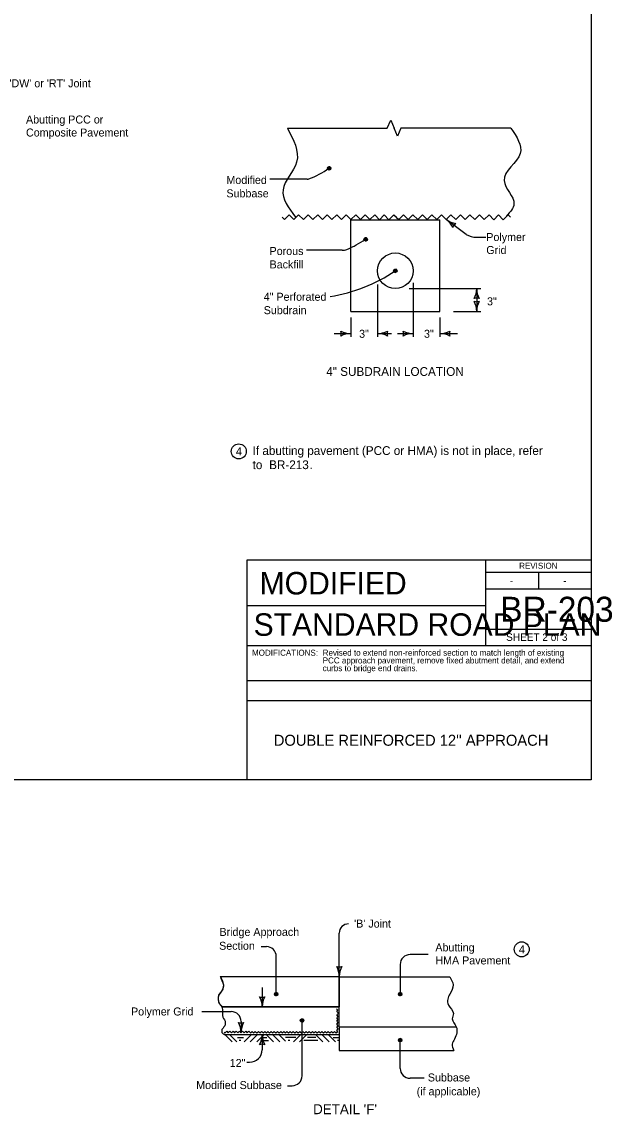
# Model space of a CAD drawing. Extents: x 5546 to 81668, y 3174 to 15999.
# Drawn here: x 15729 to 16910, y 7256 to 9440 of the extents above; entities that cross this region are included whole.
import ezdxf

# ---------------------------------------------------------------- set-up
doc = ezdxf.new("R2010")
doc.units = 0
for name, color, linetype in [('Level 61', 7, 'Continuous'), ('PS_BOLT', 7, 'Continuous'), ('PS_CONST', 7, 'Continuous'), ('PS_DIM', 7, 'Continuous'), ('PS_SHAPE', 7, 'Continuous'), ('PS_TEXT', 7, 'Continuous'), ('SheetAddenda', 7, 'Continuous'), ('tdCoLegendTitle', 7, 'Continuous'), ('tdCoShieldUsRte', 7, 'Continuous')]:
    doc.layers.add(name, color=color, linetype=linetype)

msp = doc.modelspace()

# ---------------------------------------------------------------- linework, layer by layer
at = {"layer": 'Level 61'}
msp.add_lwpolyline([(13732.5, 9944), (16867.5, 9944), (16867.5, 7924), (13732.5, 7924)], close=True, dxfattribs=at)
at = {"layer": 'PS_BOLT'}
for p, q in [((16617.8, 9014.8), (16578, 9044.5)), ((16638.4, 9009), (16656.7, 9009)), ((16440.4, 8914.6), (16440.4, 8809.9)), ((16511.7, 8918), (16511.7, 8809.9)), ((16503.4, 8906.4), (16646.9, 8906.4)), ((16638.7, 8906.4), (16638.7, 8860.8)), ((16386.9, 8848.5), (16386.9, 8809.9)), ((16565.1, 8848.5), (16565.1, 8809.9)), ((16592.5, 8860.8), (16646.9, 8860.8)), ((16353.6, 8816.4), (16386.9, 8816.4)), ((16440.4, 8816.4), (16468.3, 8816.4)), ((16480.6, 8816.4), (16511.7, 8816.4)), ((16565.1, 8816.4), (16600.3, 8816.4))]:
    msp.add_line(p, q, dxfattribs=at)
msp.add_arc((16638.4, 9048.6), 39.6, 238.7046, 270, dxfattribs=at)
at = {"layer": 'PS_CONST'}
for p, q in [((16363.9, 7530.9), (16363.9, 7617.7)), ((16207.6, 7590.7), (16218.2, 7590.7)), ((16238, 7495.7), (16238, 7570.9)), ((16542, 7574.8), (16505.5, 7574.8)), ((16485.7, 7555), (16485.7, 7495.7)), ((16209.8, 7508.8), (16209.8, 7470.4)), ((16089.2, 7460.8), (16147.8, 7460.8)), ((16167.6, 7441), (16167.6, 7418.8)), ((16289.5, 7332.3), (16289.5, 7442.8)), ((16209.8, 7414.8), (16209.8, 7384.6)), ((16485.7, 7347.3), (16485.7, 7403.7)), ((16179.2, 7359.6), (16184.8, 7359.6)), ((16533.6, 7327.5), (16505.5, 7327.5)), ((16260.7, 7312.5), (16269.7, 7312.5))]:
    msp.add_line(p, q, dxfattribs=at)
for points in [[(16240.9, 7495.4), (16240.3, 7496.6), (16239.8, 7498.4), (16237.9, 7498.8), (16236.3, 7498.5), (16234.8, 7497.4), (16235, 7495.6), (16235.2, 7493.8), (16236.7, 7492.9), (16238.2, 7492.8), (16240.2, 7493.9), (16240.4, 7495.2), (16239.9, 7497), (16238.7, 7498.5), (16237, 7498.5), (16235.6, 7497.3), (16235.5, 7495.7), (16235.8, 7493.8), (16236.8, 7493.6), (16238.1, 7493.2), (16239.6, 7494), (16239.6, 7495.4), (16239.3, 7496.9), (16238.5, 7498), (16236.9, 7497.4), (16236.1, 7496.3), (16236, 7494.8), (16236.8, 7494.4), (16237.8, 7493.9), (16239, 7494.6), (16239.2, 7495.8), (16238.7, 7496.8), (16237.6, 7496.8), (16236.8, 7496.3), (16236.5, 7495.3), (16236.9, 7494.8), (16237.5, 7494.5), (16238.4, 7495), (16238.6, 7495.7), (16238.2, 7496.4), (16237.6, 7496.3), (16237.2, 7495.8), (16237.2, 7495.1), (16237.7, 7495.1), (16238, 7495.7)], [(16488.9, 7495.5), (16488.4, 7496.6), (16487.8, 7498.4), (16485.9, 7498.8), (16484.3, 7498.5), (16482.8, 7497.4), (16483, 7495.7), (16483.2, 7493.8), (16484.7, 7493), (16486.2, 7492.8), (16488.2, 7493.9), (16488.4, 7495.2), (16487.9, 7497), (16486.8, 7498.5), (16485, 7498.5), (16483.7, 7497.3), (16483.5, 7495.7), (16483.9, 7493.8), (16484.9, 7493.6), (16486.1, 7493.2), (16487.6, 7494.1), (16487.6, 7495.4), (16487.3, 7496.9), (16486.5, 7498), (16485, 7497.4), (16484.1, 7496.3), (16484, 7494.8), (16484.9, 7494.4), (16485.8, 7493.9), (16487, 7494.7), (16487.3, 7495.8), (16486.7, 7496.8), (16485.6, 7496.9), (16484.8, 7496.3), (16484.5, 7495.3), (16484.9, 7494.8), (16485.6, 7494.5), (16486.5, 7495), (16486.6, 7495.8), (16486.2, 7496.5), (16485.6, 7496.3), (16485.2, 7495.8), (16485.2, 7495.1), (16485.8, 7495.1), (16486, 7495.7)], [(16292.7, 7442.5), (16292.2, 7443.7), (16291.6, 7445.5), (16289.8, 7445.9), (16288.2, 7445.6), (16286.7, 7444.5), (16286.8, 7442.7), (16287.1, 7440.9), (16288.5, 7440), (16290.1, 7439.9), (16292.1, 7441), (16292.2, 7442.3), (16291.8, 7444.1), (16290.6, 7445.6), (16288.9, 7445.5), (16287.5, 7444.4), (16287.3, 7442.7), (16287.7, 7440.9), (16288.7, 7440.6), (16290, 7440.3), (16291.5, 7441.1), (16291.4, 7442.5), (16291.2, 7444), (16290.3, 7445.1), (16288.8, 7444.5), (16287.9, 7443.4), (16287.9, 7441.8), (16288.7, 7441.5), (16289.6, 7441), (16290.8, 7441.7), (16291.1, 7442.9), (16290.6, 7443.9), (16289.4, 7443.9), (16288.6, 7443.4), (16288.4, 7442.4), (16288.8, 7441.9), (16289.4, 7441.6), (16290.3, 7442.1), (16290.5, 7442.8), (16290.1, 7443.5), (16289.5, 7443.4), (16289.1, 7442.9), (16289.1, 7442.2), (16289.6, 7442.2), (16289.9, 7442.8)], [(16488.9, 7403.4), (16488.4, 7404.6), (16487.8, 7406.4), (16485.9, 7406.8), (16484.3, 7406.5), (16482.8, 7405.4), (16483, 7403.6), (16483.2, 7401.8), (16484.7, 7400.9), (16486.2, 7400.8), (16488.2, 7401.9), (16488.4, 7403.2), (16487.9, 7405), (16486.8, 7406.5), (16485, 7406.5), (16483.7, 7405.3), (16483.5, 7403.7), (16483.9, 7401.8), (16484.9, 7401.6), (16486.1, 7401.2), (16487.6, 7402), (16487.6, 7403.4), (16487.3, 7404.9), (16486.5, 7406), (16485, 7405.4), (16484.1, 7404.3), (16484, 7402.8), (16484.9, 7402.4), (16485.8, 7401.9), (16487, 7402.6), (16487.3, 7403.8), (16486.7, 7404.8), (16485.6, 7404.8), (16484.8, 7404.3), (16484.5, 7403.3), (16484.9, 7402.8), (16485.6, 7402.5), (16486.5, 7403), (16486.6, 7403.7), (16486.2, 7404.4), (16485.6, 7404.3), (16485.2, 7403.8), (16485.2, 7403.1), (16485.8, 7403.1), (16486, 7403.7)]]:
    msp.add_lwpolyline(points, dxfattribs=at)
for centre in [(16237.7, 7495.7), (16485.7, 7495.7), (16289.5, 7442.8), (16485.7, 7403.7)]:
    msp.add_circle(centre, 3.47, dxfattribs=at)
for centre, radius, start, end in [((16552.5, 9010.5), 42.5, 25.1788, 53.2513), ((16603.4, 9078.6), 42.5, 233.2513, 261.3238), ((16606.5, 9023.2), 16.4, 125.5179, 160.9846), ((16382.5, 7617.7), 18.6, 90, 180), ((16218.2, 7570.9), 19.8, 0, 90), ((16505.5, 7555), 19.8, 90, 180), ((16363.9, 7566.8), 16.5, 252.2666, 287.7333), ((16321.2, 7530.9), 42.7, 360, 28.0725), ((16406.6, 7530.9), 42.7, 151.9275, 180), ((16209.8, 7506.2), 16.5, 252.2666, 287.7333), ((16167.1, 7470.4), 42.7, 360, 28.0725), ((16252.6, 7470.4), 42.7, 151.9275, 180), ((16147.8, 7441), 19.8, 0, 90), ((16167.6, 7454.6), 16.5, 252.2667, 287.7334), ((16124.8, 7418.8), 42.7, 0, 28.0725), ((16210.3, 7418.8), 42.7, 151.9275, 180), ((16167.1, 7414.8), 42.7, 331.9275, 360), ((16252.6, 7414.8), 42.7, 180, 208.0725), ((16209.8, 7378.9), 16.5, 72.2666, 107.7334), ((16505.5, 7347.3), 19.8, 180, 270), ((16269.7, 7332.3), 19.8, 270, 360)]:
    msp.add_arc(centre, radius, start, end, dxfattribs=at)
at = {"layer": 'PS_DIM'}
for p, q in [((16299.6, 9125), (16225.4, 9125)), ((16386.9, 8860.4), (16386.9, 9043.8)), ((16386.9, 9043.8), (16565.1, 9043.8)), ((16398.7, 9043.8), (16565.1, 9043.8)), ((16565.1, 8860.4), (16565.1, 9043.8)), ((16369.6, 8982.9), (16298.3, 8982.9)), ((16386.9, 8860.4), (16565.1, 8860.4)), ((16364, 7530.4), (16126.2, 7530.4)), ((16364, 7470.4), (16364, 7530.4)), ((16129, 7470.4), (16364, 7470.4)), ((16363.5, 7441.9), (16363.5, 7441.9))]:
    msp.add_line(p, q, dxfattribs=at)
for points in [[(16260.2, 9227.2), (16460, 9227.2), (16466.8, 9243.1), (16473.5, 9227.2)], [(16707.2, 9227.2), (16487.1, 9227.2), (16480.3, 9211.4), (16473.5, 9227.2)], [(16343.5, 9143.7), (16344.7, 9144.2), (16346.5, 9144.8), (16346.8, 9146.6), (16346.6, 9148.3), (16345.4, 9149.8), (16343.7, 9149.6), (16341.9, 9149.3), (16341, 9147.9), (16340.8, 9146.4), (16341.9, 9144.3), (16343.2, 9144.2), (16345.1, 9144.6), (16346.6, 9145.8), (16346.5, 9147.5), (16345.3, 9148.9), (16343.7, 9149.1), (16341.9, 9148.7), (16341.6, 9147.7), (16341.2, 9146.5), (16342.1, 9145), (16343.4, 9145), (16344.9, 9145.3), (16346, 9146.1), (16345.5, 9147.6), (16344.3, 9148.5), (16342.8, 9148.6), (16342.4, 9147.7), (16341.9, 9146.8), (16342.7, 9145.6), (16343.8, 9145.3), (16344.8, 9145.9), (16344.9, 9147), (16344.4, 9147.8), (16343.3, 9148.1), (16342.8, 9147.6), (16342.6, 9147), (16343.1, 9146.1), (16343.8, 9145.9), (16344.5, 9146.4), (16344.4, 9147), (16343.9, 9147.4), (16343.2, 9147.3), (16343.2, 9146.8), (16343.8, 9146.5)], [(16249.5, 9049.4), (16254.2, 9044.6), (16263.7, 9054.1), (16273.2, 9044.6), (16282.7, 9054.1), (16292.2, 9044.5), (16301.7, 9054), (16311.2, 9044.5), (16320.8, 9054), (16330.2, 9044.4), (16339.8, 9053.9), (16349.2, 9044.4), (16358.8, 9053.9), (16368.2, 9044.3), (16377.8, 9053.8), (16387.3, 9044.3), (16396.8, 9053.8), (16406.3, 9044.2), (16415.8, 9053.7), (16425.3, 9044.2), (16434.8, 9053.7), (16444.3, 9044.1), (16453.8, 9053.6), (16463.3, 9044.1), (16472.8, 9053.6), (16478.6, 9049)], [(16478, 9049.4), (16482.8, 9044.6), (16492.3, 9054.1), (16501.8, 9044.6), (16511.3, 9054.1), (16520.8, 9044.5), (16530.3, 9054), (16539.8, 9044.5), (16549.3, 9054), (16558.8, 9044.4), (16568.3, 9053.9), (16577.8, 9044.4), (16587.3, 9053.9), (16596.8, 9044.3), (16606.4, 9053.8), (16615.8, 9044.3), (16625.3, 9053.8), (16634.8, 9044.2), (16644.3, 9053.7), (16653.8, 9044.2), (16663.4, 9053.7), (16672.8, 9044.1), (16682.4, 9053.6), (16691.8, 9044.1), (16701.4, 9053.6), (16706.6, 9049.4)], [(16416.4, 9001.6), (16417.5, 9002.1), (16419.3, 9002.7), (16419.7, 9004.5), (16419.4, 9006.1), (16418.3, 9007.6), (16416.6, 9007.5), (16414.7, 9007.2), (16413.9, 9005.8), (16413.7, 9004.2), (16414.8, 9002.2), (16416.1, 9002.1), (16417.9, 9002.5), (16419.4, 9003.7), (16419.4, 9005.4), (16418.2, 9006.8), (16416.6, 9007), (16414.7, 9006.6), (16414.5, 9005.6), (16414.1, 9004.4), (16415, 9002.9), (16416.3, 9002.9), (16417.8, 9003.1), (16418.9, 9004), (16418.3, 9005.5), (16417.2, 9006.4), (16415.7, 9006.4), (16415.3, 9005.6), (16414.8, 9004.7), (16415.5, 9003.5), (16416.7, 9003.2), (16417.7, 9003.7), (16417.7, 9004.9), (16417.2, 9005.7), (16416.2, 9006), (16415.7, 9005.5), (16415.4, 9004.9), (16415.9, 9004), (16416.7, 9003.8), (16417.4, 9004.2), (16417.2, 9004.9), (16416.7, 9005.3), (16416, 9005.2), (16416, 9004.7), (16416.6, 9004.4)], [(16475.8, 8938.8), (16476.9, 8939.4), (16478.7, 8939.9), (16479.1, 8941.8), (16478.8, 8943.4), (16477.7, 8944.9), (16476, 8944.7), (16474.1, 8944.5), (16473.3, 8943), (16473.1, 8941.5), (16474.2, 8939.5), (16475.5, 8939.3), (16477.3, 8939.8), (16478.8, 8941), (16478.8, 8942.7), (16477.6, 8944.1), (16476, 8944.2), (16474.2, 8943.9), (16473.9, 8942.8), (16473.5, 8941.6), (16474.4, 8940.1), (16475.7, 8940.1), (16477.2, 8940.4), (16478.3, 8941.2), (16477.7, 8942.8), (16476.6, 8943.6), (16475.1, 8943.7), (16474.7, 8942.9), (16474.2, 8941.9), (16475, 8940.7), (16476.1, 8940.5), (16477.1, 8941), (16477.2, 8942.1), (16476.6, 8942.9), (16475.6, 8943.2), (16475.1, 8942.8), (16474.8, 8942.2), (16475.3, 8941.3), (16476.1, 8941.1), (16476.8, 8941.5), (16476.6, 8942.1), (16476.1, 8942.5), (16475.4, 8942.5), (16475.4, 8942), (16476, 8941.7)]]:
    msp.add_lwpolyline(points, dxfattribs=at)
for centre, radius in [((16343.8, 9146.9), 3.47), ((16416.6, 9004.8), 3.47), ((16476, 8942), 35.6), ((16476, 8942), 3.47), ((16163.1, 8580.9), 15)]:
    msp.add_circle(centre, radius, dxfattribs=at)
for centre, radius, start, end in [((16229.7, 9312.6), 200.9, 291.4956, 304.4007), ((16299.6, 9135), 10, 270, 291.4956), ((16302.5, 9170.5), 200.9, 292.4048, 304.4007), ((16369.6, 9007.9), 25, 270, 292.4048), ((16298.4, 9201.4), 314.4, 278.602, 304.4007), ((16596.2, 8906.4), 42.5, 331.9275, 360), ((16681.2, 8906.4), 42.5, 180, 208.0725), ((16638.7, 8870.7), 16.4, 72.2666, 107.7334), ((16638.7, 8896.5), 16.4, 252.2666, 287.7333), ((16596.2, 8860.8), 42.5, 360, 28.0725), ((16681.2, 8860.8), 42.5, 151.9275, 180), ((16351.3, 8816.4), 16.4, 342.2666, 17.7333), ((16386.9, 8858.9), 42.5, 241.9275, 270), ((16386.9, 8773.9), 42.5, 90, 118.0725), ((16440.4, 8858.9), 42.5, 270, 298.0725), ((16440.4, 8773.9), 42.5, 61.9275, 90), ((16476, 8816.4), 16.4, 162.2666, 197.7334), ((16476, 8816.4), 16.4, 342.2666, 17.7333), ((16511.7, 8858.9), 42.5, 241.9275, 270), ((16511.7, 8773.9), 42.5, 90, 118.0725), ((16565.1, 8858.9), 42.5, 270, 298.0725), ((16565.1, 8773.9), 42.5, 61.9275, 90), ((16600.8, 8816.4), 16.4, 162.2666, 197.7334), ((16184.8, 7384.6), 25, 270, 0)]:
    msp.add_arc(centre, radius, start, end, dxfattribs=at)
for points in [[(16260.2, 9227.2), (16278.7, 9159.4), (16251.5, 9103.8), (16276.2, 9049.4)], [(16707.2, 9227.2), (16725.7, 9176.7), (16693.6, 9122.3), (16713.3, 9075.4), (16698.5, 9051.9)]]:
    msp.add_spline(points, degree=3, dxfattribs=at)
msp.add_open_spline([(16126.2, 7530.4), (16128.1, 7525.6), (16130, 7520.7), (16132, 7515.9), (16132.8, 7513.7), (16132.3, 7511.1), (16131.8, 7508.9), (16130.4, 7502), (16123.2, 7496.4), (16122, 7489.7), (16121.4, 7486.1), (16122.1, 7481.9), (16123.5, 7478.4), (16124.6, 7475.4), (16127.3, 7473.1), (16129, 7470.4)], degree=3, dxfattribs=at)
at = {"layer": 'PS_SHAPE'}
for p, q in [((16364, 7530.4), (16125.9, 7530.4)), ((16364, 7530.4), (16584.9, 7530.4)), ((16364, 7530.4), (16364, 7470.4)), ((16364, 7470.4), (16129, 7470.4)), ((16364, 7430.4), (16364, 7470.4)), ((16364, 7430.4), (16597.7, 7430.4)), ((16364, 7430.4), (16364, 7383.1)), ((16363.5, 7414.5), (16135.9, 7414.5)), ((16135.9, 7414.5), (16149.9, 7400.5)), ((16145, 7414.5), (16159, 7400.5)), ((16172.5, 7408.3), (16160.5, 7408.3)), ((16264.9, 7414.5), (16166.4, 7414.5)), ((16187.8, 7414.5), (16173.8, 7400.5)), ((16200.1, 7414.3), (16186.1, 7400.3)), ((16213, 7414.5), (16199, 7400.5)), ((16212.4, 7409.1), (16218.9, 7409.1)), ((16218.3, 7414.5), (16232.3, 7400.5)), ((16231.2, 7414.3), (16245.2, 7400.3)), ((16243.5, 7414.5), (16256.4, 7401.7)), ((16276.8, 7409.1), (16256.6, 7409.1)), ((16286.3, 7414.5), (16272.3, 7400.5)), ((16298.6, 7414.3), (16284.6, 7400.3)), ((16317.4, 7409.1), (16300.3, 7409.1)), ((16316.9, 7414.5), (16330.9, 7400.5)), ((16329.8, 7414.3), (16343.8, 7400.3)), ((16342.1, 7414.5), (16356.1, 7400.5)), ((16351.6, 7409.1), (16363.5, 7409.1)), ((16164, 7403.4), (16167.3, 7403.4)), ((16208.6, 7403.3), (16222.7, 7403.3)), ((16261.7, 7403.4), (16264.9, 7403.4)), ((16321.2, 7403.3), (16293.4, 7403.3)), ((16360.3, 7403.4), (16360.3, 7403.4)), ((16360.3, 7403.4), (16363.5, 7403.4)), ((16364, 7383.1), (16592.8, 7383.1))]:
    msp.add_line(p, q, dxfattribs=at)
for points in [[(16361.2, 7463.8), (16358.6, 7466.4)], [(16360.7, 7420.9), (16358.8, 7422.8), (16362, 7426), (16358.8, 7429.2), (16362, 7432.3), (16358.8, 7435.5), (16362, 7438.7), (16358.8, 7441.8), (16362, 7445), (16358.9, 7448.2), (16362, 7451.3), (16358.9, 7454.5), (16362.1, 7457.7), (16358.9, 7460.8), (16361.2, 7463.8)], [(16134.1, 7419.9), (16135.7, 7418.3), (16138.9, 7421.5), (16142, 7418.3), (16145.2, 7421.5), (16148.4, 7418.3), (16151.5, 7421.4), (16154.7, 7418.3), (16157.9, 7421.4), (16161, 7418.2), (16164.2, 7421.4), (16167.4, 7418.2), (16170.5, 7421.4), (16173.7, 7418.2), (16176.9, 7421.4), (16180, 7418.2), (16183.2, 7421.4), (16186.4, 7418.2), (16189.6, 7421.3), (16192.7, 7418.2), (16195.9, 7421.3), (16199, 7418.2), (16202.2, 7421.3), (16205.4, 7418.1), (16208.6, 7421.3), (16210, 7420.2)], [(16210.3, 7419.8), (16211.9, 7418.2), (16215.1, 7421.3), (16218.2, 7418.2), (16221.4, 7421.3), (16224.6, 7418.1), (16227.7, 7421.3), (16230.9, 7418.1), (16234.1, 7421.3), (16237.2, 7418.1), (16240.4, 7421.3), (16243.6, 7418.1), (16246.8, 7421.3), (16249.9, 7418.1), (16253.1, 7421.2), (16256.3, 7418.1), (16259.4, 7421.2), (16262.6, 7418), (16265.8, 7421.2), (16268.9, 7418), (16272.1, 7421.2), (16275.3, 7418), (16278.4, 7421.2), (16281.6, 7418), (16284.8, 7421.2), (16286.6, 7419.7)], [(16286.6, 7419.7), (16288.2, 7418.2), (16291.3, 7421.3), (16294.5, 7418.1), (16297.7, 7421.3), (16300.8, 7418.1), (16304, 7421.3), (16307.2, 7418.1), (16310.3, 7421.3), (16313.5, 7418.1), (16316.7, 7421.3), (16319.8, 7418.1), (16323, 7421.2), (16326.2, 7418.1), (16329.4, 7421.2), (16332.5, 7418), (16335.7, 7421.2), (16338.9, 7418), (16342, 7421.2), (16345.2, 7418), (16348.4, 7421.2), (16351.5, 7418), (16354.7, 7421.1), (16357.9, 7418), (16360.8, 7420.9)]]:
    msp.add_lwpolyline(points, dxfattribs=at)
for points in [[(16125.9, 7531.2), (16132, 7515.9), (16131.8, 7508.9), (16122, 7489.7), (16123.5, 7478.4), (16130, 7468.3), (16130.6, 7452.8), (16135.9, 7441.9)], [(16584.9, 7530.4), (16591.4, 7514), (16585.3, 7495.8), (16580.8, 7485.9), (16582.3, 7473.7), (16592.2, 7457), (16589.9, 7446.3), (16597.7, 7430.4), (16594.4, 7406), (16589.9, 7395.4), (16592.8, 7383.1)], [(16135.9, 7441.9), (16135.9, 7435.4), (16129.4, 7425.2)], [(16129.4, 7425.2), (16129.4, 7418.8), (16135.9, 7414.5)]]:
    msp.add_spline(points, degree=3, dxfattribs=at)
at = {"layer": 'PS_TEXT'}
msp.add_circle((16728.7, 7585.3), 15, dxfattribs=at)
at = {"layer": 'tdCoLegendTitle'}
for p, q in [((16656.6, 8364), (16656.6, 8272.7)), ((16656.6, 8339.1), (16867.5, 8339.1)), ((16762.1, 8339.1), (16762.1, 8305.9)), ((16656.6, 8305.9), (16867.5, 8305.9)), ((16179.5, 8272.7), (16656.6, 8272.7)), ((16656.6, 8272.7), (16656.6, 8192.7)), ((16867.5, 8224.9), (16656.6, 8224.9)), ((16179.5, 8192.7), (16867.5, 8192.7)), ((16179.5, 8122.7), (16867.5, 8122.7)), ((16179.5, 8082.7), (16867.5, 8082.7)), ((16179.5, 8082.7), (16867.5, 8082.7))]:
    msp.add_line(p, q, dxfattribs=at)
msp.add_lwpolyline([(16179.5, 8364), (16867.5, 8364), (16867.5, 7924), (16179.5, 7924)], close=True, dxfattribs=at)

# ---------------------------------------------------------------- texts
at = {"layer": 'PS_BOLT'}
for s, height, p in [('Modified', 16, (16138.3, 9115.6)), ('Subbase', 16, (16138.3, 9088.8)), ('Polymer ', 16, (16657.9, 9001.4)), ('Porous', 16, (16224.6, 8973.5)), ('Grid', 16, (16657.9, 8975.4)), ('Backfill', 16, (16224.6, 8946.7)), ('4" Perforated ', 16, (16212.9, 8882)), ('3"', 16, (16659.4, 8872.9)), ('Subdrain', 16, (16212.9, 8855.2)), ('3"', 16, (16403.6, 8808)), ('3"', 16, (16533.4, 8808)), ("DETAIL 'F'", 20, (16311.7, 7255.7))]:
    msp.add_text(s, height=height, dxfattribs=at).set_placement(p)
at = {"layer": 'PS_CONST'}
for s, p in [("'DW' or 'RT' Joint", (15704.5, 9308.8)), ('Abutting PCC or', (15737.6, 9236.4)), ('Composite Pavement', (15737.6, 9210.4)), ("'B' Joint", (16393.7, 7628.7)), ('Bridge Approach', (16124.4, 7612.1)), ('Section', (16123.8, 7584.4)), ('Abutting', (16556.1, 7581.1)), ('HMA Pavement', (16556.1, 7555.1)), ('Polymer Grid', (15947.6, 7453)), ('12"', (16144.9, 7350.1)), ('Modified Subbase', (16077.9, 7305.9)), ('Subbase', (16541.1, 7321.1)), ('(if applicable)', (16518.7, 7293.4))]:
    msp.add_text(s, height=16, dxfattribs=at).set_placement(p)
at = {"layer": 'PS_DIM'}
for s, height, p in [('4" SUBDRAIN LOCATION', 17.5, (16338, 8731.8)), ('4', 16, (16157.3, 8572.9))]:
    msp.add_text(s, height=height, dxfattribs=at).set_placement(p)
at = {"layer": 'PS_TEXT'}
msp.add_text('4', height=16, dxfattribs=at).set_placement((16723.1, 7577.3))
at = {"layer": 'SheetAddenda'}
for s, p in [('If abutting pavement (PCC or HMA) is not in place, refer ', (16190.7, 8573.7)), ('to ', (16190.7, 8545.4)), ('BR-213', (16223.7, 8545.4)), ('BR-213', (16223.7, 8545.4)), ('.', (16304.3, 8545.4))]:
    msp.add_text(s, height=17.5, dxfattribs=at).set_placement(p)
at = {"layer": 'tdCoLegendTitle'}
for s, height, p in [('REVISION', 12, (16723.6, 8346.2)), ('-', 15, (16705.1, 8314.7)), ('-', 15, (16811.6, 8315.1)), ('BR-203', 50, (16685.8, 8240.2)), ('STANDARD ROAD PLAN', 45.001, (16192.6, 8212.1)), ('SHEET 2 of 3', 15, (16697.6, 8202)), ('Revised to extend non-reinforced section to match length of existing ', 12, (16330.8, 8172.4)), ('PCC approach pavement, remove fixed abutment detail, and extend ', 12, (16330.8, 8156.9)), ('curbs to bridge end drains.', 12, (16330.8, 8141.4)), ("DOUBLE REINFORCED 12'' APPROACH", 22, (16233, 7992.3))]:
    msp.add_text(s, height=height, dxfattribs=at).set_placement(p)
at = {"layer": 'tdCoShieldUsRte'}
for s, height, p in [('MODIFIED', 45, (16204.6, 8294.8)), ('MODIFICATIONS:', 12, (16189.5, 8172.3))]:
    msp.add_text(s, height=height, dxfattribs=at).set_placement(p)

doc.saveas('drawing.dxf')
